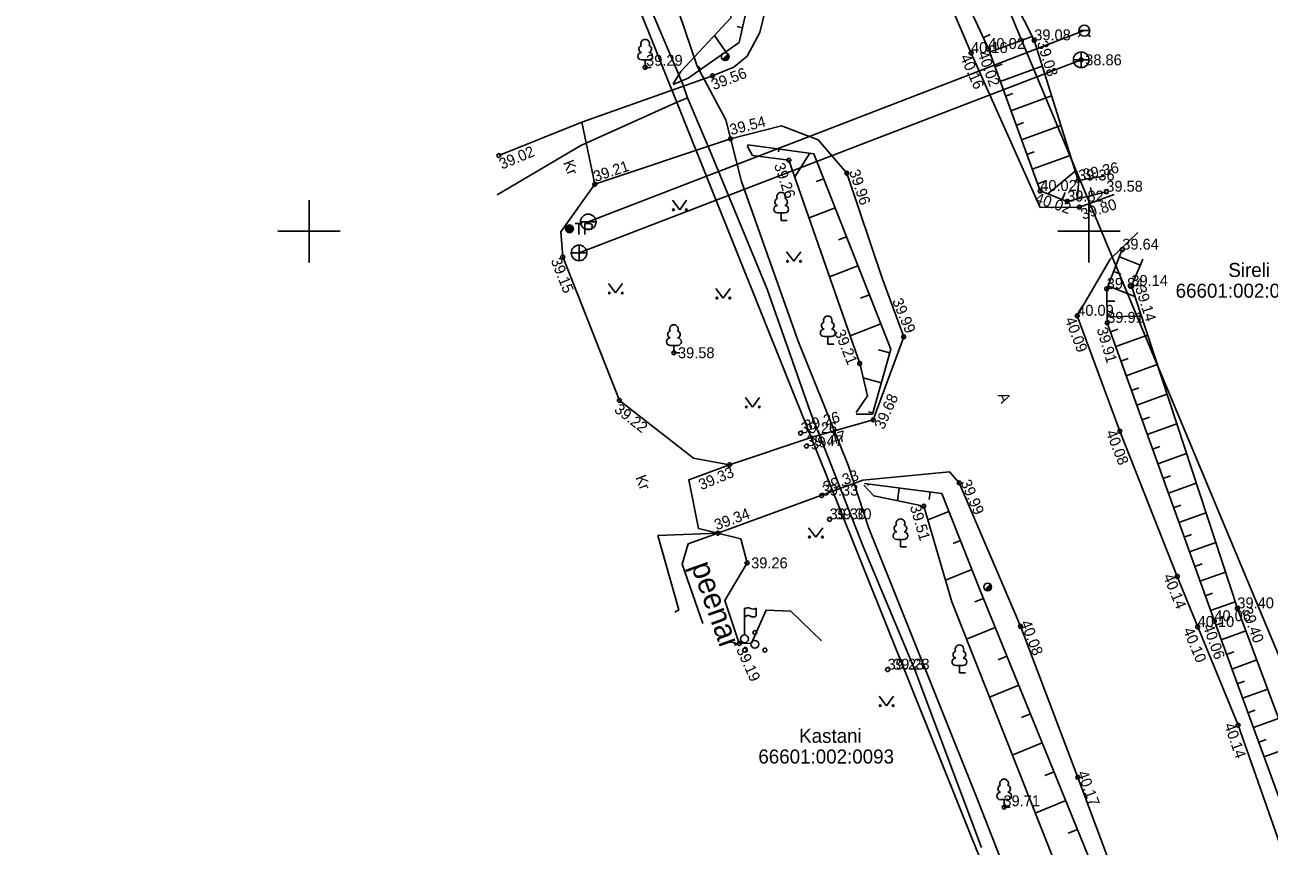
# Model space of a CAD drawing. Extents: x 627548 to 628052, y 6467984 to 6468802.
# Drawn here: x 627831.8 to 627911.6, y 6468260.5 to 6468313.2 of the extents above; entities that cross this region are included whole.
import ezdxf

# ---------------------------------------------------------------- set-up
doc = ezdxf.new("R2010")
doc.units = 0
for name, color, linetype in [('HALJASTUS', 7, 'Continuous'), ('KKAEV', 7, 'Continuous'), ('KORGUS-EH2000', 7, 'Continuous'), ('KTRASS', 7, 'Continuous'), ('MOOTKORG-EH2000', 7, 'Continuous'), ('MOOTMPUNKT', 7, 'Continuous'), ('PIIR', 7, 'Continuous'), ('POST', 7, 'Continuous'), ('PUU', 7, 'Continuous'), ('RAJATIS', 7, 'Continuous'), ('RELJEEF', 7, 'Continuous'), ('SITRASS', 7, 'Continuous'), ('TEE', 7, 'Continuous'), ('VKAEV', 7, 'Continuous'), ('VORK', 7, 'Continuous'), ('VTRASS', 7, 'Continuous')]:
    doc.layers.add(name, color=color, linetype=linetype)

msp = doc.modelspace()

# ---------------------------------------------------------------- linework, layer by layer
at = {"layer": 'HALJASTUS'}
for p, q in [((627873.299, 6468301.984), (627873.762, 6468301.377)), ((627873.762, 6468301.377), (627874.208, 6468301.984)), ((627880.62, 6468298.678), (627881.083, 6468298.071)), ((627881.083, 6468298.071), (627881.529, 6468298.678)), ((627869.19, 6468296.647), (627869.653, 6468296.04)), ((627869.653, 6468296.04), (627870.099, 6468296.647)), ((627876.086, 6468296.316), (627876.549, 6468295.71)), ((627876.549, 6468295.71), (627876.995, 6468296.316)), ((627877.975, 6468289.326), (627878.438, 6468288.72)), ((627878.438, 6468288.72), (627878.884, 6468289.326)), ((627882.025, 6468280.978), (627882.488, 6468280.372)), ((627882.488, 6468280.372), (627882.934, 6468280.978)), ((627886.559, 6468270.163), (627887.022, 6468269.556)), ((627887.022, 6468269.556), (627887.468, 6468270.163))]:
    msp.add_line(p, q, dxfattribs=at)
msp.add_lwpolyline([(627873.919, 6468278.628), (627874.303, 6468279.942), (627876.206, 6468280.62), (627877.677, 6468280.262), (627878.082, 6468278.718), (627876.666, 6468276.298), (627877.586, 6468273.55), (627878.366, 6468273.568), (627879.299, 6468275.694), (627880.884, 6468275.618), (627882.857, 6468273.714)], dxfattribs=at)
for centre in [(627873.361, 6468301.377), (627874.19, 6468301.377), (627880.682, 6468298.071), (627881.511, 6468298.071), (627869.252, 6468296.04), (627870.081, 6468296.04), (627876.148, 6468295.71), (627876.977, 6468295.71), (627878.037, 6468288.72), (627878.866, 6468288.72), (627882.087, 6468280.372), (627882.916, 6468280.372), (627886.621, 6468269.556), (627887.45, 6468269.556)]:
    msp.add_circle(centre, 0.055, dxfattribs=at)
at = {"layer": 'KKAEV'}
for p, q in [((627899.506, 6468310.497), (627899.506, 6468311.497)), ((627899.006, 6468310.997), (627900.006, 6468310.997)), ((627866.811, 6468298.611), (627867.811, 6468298.611)), ((627867.311, 6468298.111), (627867.311, 6468299.111))]:
    msp.add_line(p, q, dxfattribs=at)
for centre in [(627899.506, 6468310.997), (627867.311, 6468298.611)]:
    msp.add_circle(centre, 0.5, dxfattribs=at)
at = {"layer": 'KORGUS-EH2000'}
for centre in [(627871.551, 6468310.515), (627899.506, 6468310.997), (627875.866, 6468309.978), (627877.023, 6468305.93), (627862.168, 6468304.855), (627880.767, 6468304.558), (627884.478, 6468303.721), (627868.314, 6468303.013), (627899.39, 6468301.545), (627866.262, 6468298.348), (627888.125, 6468293.223), (627873.393, 6468292.203), (627885.303, 6468291.516), (627869.897, 6468289.144), (627886.174, 6468287.898), (627901.988, 6468287.172), (627876.962, 6468285.017), (627891.69, 6468283.856), (627889.411, 6468282.354), (627876.206, 6468280.62), (627878.082, 6468278.718), (627905.673, 6468277.849), (627895.618, 6468274.651), (627877.586, 6468273.55), (627909.567, 6468268.305), (627899.293, 6468264.957), (627894.568, 6468263.052)]:
    msp.add_circle(centre, 0.125, dxfattribs=at)
at = {"layer": 'KTRASS'}
msp.add_line((627867.311, 6468298.611), (627899.506, 6468310.997), dxfattribs=at)
at = {"layer": 'MOOTMPUNKT'}
for centre in [(627896.498, 6468312.249), (627892.446, 6468311.434), (627893.555, 6468311.693), (627899.309, 6468303.257), (627896.884, 6468302.582), (627901.118, 6468302.536), (627898.609, 6468301.907), (627902.143, 6468298.82), (627901.144, 6468296.301), (627902.726, 6468296.488), (627899.253, 6468294.574), (627901.175, 6468294.123), (627881.512, 6468287.043), (627881.89, 6468286.213), (627882.869, 6468283.039), (627883.368, 6468281.515), (627909.522, 6468275.801), (627906.975, 6468274.61), (627908.047, 6468274.979), (627887.093, 6468271.873)]:
    msp.add_circle(centre, 0.125, dxfattribs=at)
at = {"layer": 'PIIR'}
for p, q in [((627869.12, 6468319.4), (627897.87, 6468247.69)), ((627912.59, 6468271.79), (627893.5, 6468317.49))]:
    msp.add_line(p, q, dxfattribs=at)
at = {"layer": 'POST'}
for p, q in [((627876.506, 6468311.02), (627876.86, 6468311.373)), ((627867.051, 6468300.496), (627867.518, 6468300.496)), ((627867.284, 6468300.496), (627867.284, 6468299.796)), ((627867.684, 6468300.496), (627867.684, 6468299.796)), ((627893.334, 6468276.992), (627893.688, 6468277.345))]:
    msp.add_line(p, q, dxfattribs=at)
msp.add_lwpolyline([(627867.684, 6468300.496), (627867.984, 6468300.496), (627868.084, 6468300.463), (627868.118, 6468300.43), (627868.151, 6468300.363), (627868.151, 6468300.263), (627868.118, 6468300.196), (627868.084, 6468300.163), (627867.984, 6468300.13), (627867.684, 6468300.13)], dxfattribs=at)
for centre, radius in [((627876.683, 6468311.196), 0.25), ((627866.692, 6468300.149), 0.25), ((627866.692, 6468300.149), 0.225), ((627866.692, 6468300.149), 0.2), ((627866.692, 6468300.149), 0.175), ((627866.692, 6468300.149), 0.15), ((627866.692, 6468300.149), 0.125), ((627866.692, 6468300.149), 0.1), ((627866.692, 6468300.149), 0.075), ((627866.692, 6468300.149), 0.05), ((627866.692, 6468300.149), 0.025), ((627893.511, 6468277.168), 0.25)]:
    msp.add_circle(centre, radius, dxfattribs=at)
for centre, radius, start, end in [((627876.683, 6468311.196), 0.225, 224.85406, 45.03563), ((627876.683, 6468311.196), 0.2, 224.84272, 45.04698), ((627876.683, 6468311.196), 0.175, 224.82813, 45.06157), ((627876.683, 6468311.196), 0.15, 224.80867, 45.08103), ((627876.683, 6468311.196), 0.125, 224.78144, 45.10826), ((627876.683, 6468311.196), 0.1, 224.74058, 45.14911), ((627876.683, 6468311.196), 0.075, 224.67249, 45.2172), ((627876.683, 6468311.196), 0.05, 224.53632, 45.35338), ((627876.683, 6468311.196), 0.025, 224.12776, 45.76193), ((627893.511, 6468277.168), 0.225, 224.85406, 45.03563), ((627893.511, 6468277.168), 0.2, 224.84272, 45.04698), ((627893.511, 6468277.168), 0.175, 224.82813, 45.06157), ((627893.511, 6468277.168), 0.15, 224.80867, 45.08103), ((627893.511, 6468277.168), 0.125, 224.78144, 45.10826), ((627893.511, 6468277.168), 0.1, 224.74058, 45.14911), ((627893.511, 6468277.168), 0.075, 224.67249, 45.2172), ((627893.511, 6468277.168), 0.05, 224.53632, 45.35338), ((627893.511, 6468277.168), 0.025, 224.12776, 45.76193)]:
    msp.add_arc(centre, radius, start, end, dxfattribs=at)
at = {"layer": 'PUU'}
for p, q in [((627871.791, 6468310.99), (627871.311, 6468310.99)), ((627871.551, 6468310.515), (627871.551, 6468310.99)), ((627871.931, 6468310.515), (627871.551, 6468310.515)), ((627880.509, 6468301.173), (627880.029, 6468301.173)), ((627880.269, 6468300.698), (627880.269, 6468301.173)), ((627880.649, 6468300.698), (627880.269, 6468300.698)), ((627883.497, 6468293.238), (627883.017, 6468293.238)), ((627883.257, 6468292.763), (627883.257, 6468293.238)), ((627873.633, 6468292.678), (627873.153, 6468292.678)), ((627873.393, 6468292.203), (627873.393, 6468292.678)), ((627873.773, 6468292.203), (627873.393, 6468292.203)), ((627883.637, 6468292.763), (627883.257, 6468292.763)), ((627888.158, 6468280.227), (627887.678, 6468280.227)), ((627887.918, 6468279.752), (627887.918, 6468280.227)), ((627888.298, 6468279.752), (627887.918, 6468279.752)), ((627891.939, 6468272.132), (627891.459, 6468272.132)), ((627891.699, 6468271.657), (627891.699, 6468272.132)), ((627892.079, 6468271.657), (627891.699, 6468271.657)), ((627894.808, 6468263.527), (627894.328, 6468263.527)), ((627894.568, 6468263.052), (627894.568, 6468263.527)), ((627894.948, 6468263.052), (627894.568, 6468263.052))]:
    msp.add_line(p, q, dxfattribs=at)
for centre, radius in [((627878.579, 6468273.497), 0.25), ((627878.579, 6468274.247), 0.125), ((627877.929, 6468273.122), 0.125), ((627879.229, 6468273.122), 0.125)]:
    msp.add_circle(centre, radius, dxfattribs=at)
for centre, radius, start, end in [((627871.551, 6468312.035), 0.277, 332.5799, 207.4201), ((627871.314, 6468311.227), 0.238, 90.0016, 269.3953), ((627871.381, 6468311.688), 0.233, 109.02174, 253.14154), ((627871.721, 6468311.688), 0.233, 286.85082, 70.98591), ((627871.788, 6468311.227), 0.238, 270.6047, 89.9984), ((627880.269, 6468302.218), 0.277, 332.5799, 207.4201), ((627880.032, 6468301.41), 0.238, 90.0016, 269.3953), ((627880.099, 6468301.871), 0.233, 109.02174, 253.14154), ((627880.439, 6468301.871), 0.233, 286.85082, 70.98591), ((627880.506, 6468301.41), 0.238, 270.6047, 89.9984), ((627883.257, 6468294.283), 0.277, 332.5799, 207.4201), ((627873.223, 6468293.376), 0.233, 109.02174, 253.14154), ((627873.393, 6468293.723), 0.277, 332.5799, 207.4201), ((627873.563, 6468293.376), 0.233, 286.85082, 70.98591), ((627883.02, 6468293.475), 0.238, 90.0016, 269.3953), ((627883.087, 6468293.936), 0.233, 109.02174, 253.14154), ((627883.427, 6468293.936), 0.233, 286.85082, 70.98591), ((627883.494, 6468293.475), 0.238, 270.6047, 89.9984), ((627873.156, 6468292.915), 0.238, 90.0016, 269.3953), ((627873.63, 6468292.915), 0.238, 270.6047, 89.9984), ((627887.748, 6468280.925), 0.233, 109.02174, 253.14154), ((627887.918, 6468281.272), 0.277, 332.5799, 207.4201), ((627888.088, 6468280.925), 0.233, 286.85082, 70.98591), ((627887.681, 6468280.464), 0.238, 90.0016, 269.3953), ((627888.155, 6468280.464), 0.238, 270.6047, 89.9984), ((627891.529, 6468272.83), 0.233, 109.02174, 253.14154), ((627891.699, 6468273.177), 0.277, 332.5799, 207.4201), ((627891.869, 6468272.83), 0.233, 286.85082, 70.98591), ((627891.462, 6468272.369), 0.238, 90.0016, 269.3953), ((627891.936, 6468272.369), 0.238, 270.6047, 89.9984), ((627894.398, 6468264.225), 0.233, 109.02174, 253.14154), ((627894.568, 6468264.572), 0.277, 332.5799, 207.4201), ((627894.738, 6468264.225), 0.233, 286.85082, 70.98591), ((627894.331, 6468263.764), 0.238, 90.0016, 269.3953), ((627894.805, 6468263.764), 0.238, 270.6047, 89.9984)]:
    msp.add_arc(centre, radius, start, end, dxfattribs=at)
at = {"layer": 'RAJATIS'}
for p, q in [((627877.922, 6468274.094), (627877.922, 6468275.844)), ((627878.675, 6468275.813), (627878.675, 6468275.313))]:
    msp.add_line(p, q, dxfattribs=at)
msp.add_circle((627877.922, 6468273.844), 0.25, dxfattribs=at)
for centre, radius, start, end in [((627878.145, 6468275.559), 0.288, 57.89407, 140.73656), ((627878.145, 6468275.059), 0.288, 57.89407, 140.73656), ((627878.479, 6468276.092), 0.341, 237.89407, 305.02189), ((627878.479, 6468275.592), 0.341, 237.89407, 305.02189)]:
    msp.add_arc(centre, radius, start, end, dxfattribs=at)
at = {"layer": 'RELJEEF'}
for p, q in [((627877.784, 6468313.056), (627877.453, 6468313.129)), ((627876.728, 6468311.519), (627875.995, 6468312.565)), ((627893.226, 6468312.405), (627893.68, 6468312.615)), ((627893.629, 6468311.491), (627896.374, 6468312.494)), ((627875.09, 6468310.371), (627874.943, 6468310.581)), ((627893.972, 6468310.551), (627894.442, 6468310.723)), ((627894.315, 6468309.612), (627897.014, 6468310.598)), ((627894.659, 6468308.673), (627895.128, 6468308.844)), ((627895.002, 6468307.734), (627897.611, 6468308.687)), ((627895.345, 6468306.794), (627895.815, 6468306.966)), ((627895.688, 6468305.855), (627898.209, 6468306.776)), ((627878.135, 6468305.54), (627878.12, 6468305.425)), ((627880.117, 6468305.276), (627880.093, 6468305.089)), ((627882.1, 6468305.012), (627881.139, 6468303.489)), ((627896.031, 6468304.916), (627896.501, 6468305.087)), ((627896.374, 6468303.977), (627898.806, 6468304.865)), ((627883.003, 6468303.37), (627882.522, 6468303.182)), ((627896.718, 6468303.037), (627897.187, 6468303.209)), ((627897.364, 6468302.394), (627899.123, 6468303.853)), ((627899.252, 6468302.068), (627899.357, 6468303.265)), ((627898.295, 6468302.03), (627898.477, 6468302.495)), ((627900.222, 6468302.311), (627900.1, 6468302.796)), ((627883.733, 6468301.508), (627882.056, 6468300.851)), ((627884.463, 6468299.646), (627883.938, 6468299.441)), ((627885.193, 6468297.784), (627883.371, 6468297.07)), ((627901.959, 6468298.355), (627903.353, 6468297.802)), ((627901.59, 6468297.426), (627902.055, 6468297.241)), ((627901.221, 6468296.496), (627902.948, 6468295.811)), ((627885.923, 6468295.922), (627885.355, 6468295.7)), ((627901.155, 6468295.511), (627901.655, 6468295.518)), ((627901.169, 6468294.511), (627903.365, 6468294.542)), ((627886.653, 6468294.06), (627884.686, 6468293.289)), ((627901.382, 6468293.547), (627901.852, 6468293.716)), ((627901.72, 6468292.606), (627903.761, 6468293.339)), ((627887.228, 6468292.191), (627886.51, 6468292.393)), ((627902.057, 6468291.665), (627902.528, 6468291.834)), ((627902.395, 6468290.723), (627904.385, 6468291.438)), ((627886.685, 6468290.266), (627885.523, 6468290.594)), ((627902.733, 6468289.782), (627903.204, 6468289.951)), ((627903.071, 6468288.841), (627905.01, 6468289.537)), ((627886.142, 6468288.341), (627885.87, 6468288.418)), ((627903.409, 6468287.9), (627903.879, 6468288.069)), ((627903.747, 6468286.959), (627905.634, 6468287.636)), ((627904.085, 6468286.017), (627904.555, 6468286.186)), ((627904.422, 6468285.076), (627906.258, 6468285.735)), ((627904.76, 6468284.135), (627905.231, 6468284.304)), ((627885.851, 6468283.786), (627885.837, 6468283.683)), ((627887.834, 6468283.523), (627887.725, 6468282.702)), ((627889.816, 6468283.261), (627889.754, 6468282.788)), ((627905.098, 6468283.194), (627906.883, 6468283.835)), ((627905.436, 6468282.253), (627905.907, 6468282.422)), ((627891.027, 6468282.009), (627889.669, 6468281.472)), ((627905.774, 6468281.311), (627907.507, 6468281.934)), ((627891.763, 6468280.15), (627891.304, 6468279.968)), ((627906.112, 6468280.37), (627906.582, 6468280.539)), ((627906.45, 6468279.429), (627908.132, 6468280.033)), ((627906.787, 6468278.488), (627907.258, 6468278.657)), ((627892.499, 6468278.29), (627890.798, 6468277.617)), ((627907.125, 6468277.547), (627908.756, 6468278.132)), ((627893.241, 6468276.433), (627892.694, 6468276.21)), ((627907.463, 6468276.606), (627907.934, 6468276.774)), ((627907.801, 6468275.664), (627909.381, 6468276.231)), ((627893.995, 6468274.58), (627892.151, 6468273.829)), ((627908.141, 6468274.724), (627908.61, 6468274.896)), ((627908.484, 6468273.785), (627910.061, 6468274.362)), ((627908.828, 6468272.846), (627909.298, 6468273.018)), ((627894.75, 6468272.728), (627894.191, 6468272.5)), ((627909.172, 6468271.907), (627910.764, 6468272.49)), ((627895.505, 6468270.876), (627893.621, 6468270.109)), ((627909.516, 6468270.968), (627909.986, 6468271.14)), ((627909.86, 6468270.029), (627911.466, 6468270.617)), ((627896.259, 6468269.024), (627895.688, 6468268.791)), ((627910.204, 6468269.09), (627910.674, 6468269.262)), ((627910.548, 6468268.151), (627912.168, 6468268.744)), ((627910.892, 6468267.212), (627911.362, 6468267.384)), ((627897.014, 6468267.172), (627895.09, 6468266.388)), ((627911.236, 6468266.273), (627912.871, 6468266.872)), ((627897.768, 6468265.32), (627897.185, 6468265.082)), ((627898.523, 6468263.467), (627896.559, 6468262.667)), ((627899.277, 6468261.615), (627898.682, 6468261.373))]:
    msp.add_line(p, q, dxfattribs=at)
for points in [[(627872.236, 6468374.908), (627868.619, 6468372.938), (627874.455, 6468357.057), (627883.906, 6468332.57), (627893.555, 6468311.693), (627896.884, 6468302.582), (627898.609, 6468301.907), (627901.118, 6468302.536)], [(627872.45, 6468373.949), (627870.95, 6468372.302), (627876.843, 6468358.333), (627885.562, 6468333.781), (627896.498, 6468312.249), (627899.309, 6468303.257), (627900.953, 6468303.542)], [(627873.347, 6468309.45), (627873.83, 6468310.241), (627877.069, 6468313.719), (627876.234, 6468317.068), (627866.378, 6468340.34), (627864.296, 6468344.897), (627863.023, 6468347.157)], [(627873.346, 6468309.415), (627874.307, 6468309.823), (627877.573, 6468312.111), (627878.237, 6468315.09), (627877.354, 6468317.55), (627868.906, 6468339.736), (627866.293, 6468345.533)], [(627878.118, 6468305.428), (627878.438, 6468304.86), (627880.767, 6468304.558), (627885.303, 6468291.516), (627885.799, 6468289.434), (627885.077, 6468288.359)], [(627878.135, 6468305.54), (627882.374, 6468304.975), (627887.294, 6468292.425), (627886.12, 6468288.264), (627885.077, 6468288.259)], [(627902.143, 6468298.82), (627901.144, 6468296.301), (627901.175, 6468294.123), (627908.047, 6468274.979), (627912.743, 6468262.16), (627914.112, 6468261.408), (627915.818, 6468261.36), (627916.836, 6468261.596)], [(627903.454, 6468298.207), (627902.726, 6468296.488), (627909.522, 6468275.801), (627914.133, 6468263.505), (627915.522, 6468263.197)], [(627885.568, 6468283.7), (627886.202, 6468283.017), (627889.411, 6468282.354), (627891.208, 6468276.218), (627898.343, 6468258.151), (627903.422, 6468243.916), (627907.954, 6468231.1), (627910.914, 6468222.474), (627911.053, 6468221.789), (627909.271, 6468220.222)], [(627908.534, 6468218.999), (627909.815, 6468219.296), (627912.114, 6468220.934), (627912.832, 6468222.373), (627910.285, 6468232.435), (627905.813, 6468244.778), (627900.201, 6468259.348), (627892.991, 6468277.046), (627890.571, 6468283.161), (627885.622, 6468283.816)]]:
    msp.add_lwpolyline(points, dxfattribs=at)
at = {"layer": 'SITRASS'}
for points in [[(627895.041, 6468257.946), (627892.765, 6468263.751), (627885.861, 6468280.997), (627884.574, 6468284.991), (627881.355, 6468292.946), (627877.718, 6468303.187), (627876.72, 6468307.148), (627874.885, 6468310.594), (627872.6, 6468317.358), (627865.068, 6468335.844), (627862.702, 6468343.386), (627859.888, 6468348.841), (627858.632, 6468350.621)], [(627893.107, 6468260.449), (627888.841, 6468271.867), (627885.53, 6468279.764), (627882.135, 6468288.441), (627879.374, 6468296.292), (627875.722, 6468305.138), (627874.264, 6468308.557), (627873.961, 6468309.445), (627871.602, 6468314.968), (627869.468, 6468319.018), (627867.454, 6468324.77), (627864.183, 6468335.69), (627861.634, 6468344.011), (627861.623, 6468344.046)], [(627874.264, 6468308.557), (627873.441, 6468308.226), (627867.426, 6468305.507), (627862.053, 6468302.34)]]:
    msp.add_lwpolyline(points, dxfattribs=at)
at = {"layer": 'TEE'}
for points in [[(627773.875, 6468550.47), (627771.331, 6468547.778), (627770.184, 6468544.969), (627779.724, 6468530.382), (627790.194, 6468514.89), (627795.603, 6468506.268), (627810.358, 6468482.16), (627820.252, 6468465.61), (627824.787, 6468457.176), (627842.022, 6468424.68), (627853.219, 6468402.014), (627861.194, 6468384.862), (627867.233, 6468371.168), (627873.073, 6468356.381), (627889.258, 6468318.908), (627892.446, 6468311.434), (627896.87, 6468301.517), (627899.405, 6468301.54), (627901.626, 6468302.361)], [(627850.995, 6468383.192), (627865.917, 6468348.418), (627869.848, 6468339.563), (627875.198, 6468325.862), (627878.868, 6468316.397), (627879.191, 6468315.536), (627879.247, 6468314.16), (627878.907, 6468312.752), (627878.096, 6468311.241), (627877.224, 6468310.534), (627875.866, 6468309.978), (627867.479, 6468306.988), (627868.314, 6468303.013), (627877.023, 6468305.93), (627880.299, 6468306.759), (627882.65, 6468305.874), (627884.478, 6468303.721), (627886.739, 6468296.981), (627888.125, 6468293.223), (627886.174, 6468287.898), (627882.32, 6468286.813)], [(627867.479, 6468306.988), (627862.168, 6468304.855)], [(627866.143, 6468299.952), (627868.314, 6468303.013)], [(627882.32, 6468286.813), (627876.962, 6468285.017), (627874.642, 6468285.428), (627869.897, 6468289.144), (627866.262, 6468298.348), (627866.143, 6468299.952)], [(627917.783, 6468261.132), (627915.406, 6468260.556), (627912.243, 6468260.69), (627909.567, 6468268.305), (627905.673, 6468277.849), (627901.988, 6468287.172), (627899.253, 6468294.574), (627901.367, 6468298.21), (627903.149, 6468299.908)], [(627876.962, 6468285.017), (627874.347, 6468284.039), (627874.971, 6468280.918), (627876.206, 6468280.62), (627885.515, 6468284.028), (627891.073, 6468284.568), (627891.69, 6468283.856), (627895.618, 6468274.651), (627899.293, 6468264.957), (627902.839, 6468255.421), (627906.501, 6468245.876), (627910.238, 6468235.996), (627913.742, 6468226.218), (627914.642, 6468222.923), (627913.271, 6468221.098), (627910.191, 6468218.684), (627908.74, 6468217.99)], [(627876.206, 6468280.62), (627872.364, 6468280.485), (627873.713, 6468275.697), (627873.443, 6468275.566)], [(627873.919, 6468278.628), (627875.251, 6468274.826)]]:
    msp.add_lwpolyline(points, dxfattribs=at)
at = {"layer": 'VKAEV'}
for p, q in [((627899.352, 6468312.87), (627900.052, 6468312.87)), ((627899.455, 6468312.623), (627899.315, 6468312.483)), ((627899.949, 6468312.623), (627900.089, 6468312.483)), ((627867.398, 6468300.601), (627868.398, 6468300.601))]:
    msp.add_line(p, q, dxfattribs=at)
for centre, radius in [((627899.702, 6468312.87), 0.35), ((627867.898, 6468300.601), 0.5)]:
    msp.add_circle(centre, radius, dxfattribs=at)
at = {"layer": 'VORK'}
for p, q in [((627850, 6468302), (627850, 6468298)), ((627900, 6468302), (627900, 6468298)), ((627848, 6468300), (627852, 6468300)), ((627898, 6468300), (627902, 6468300))]:
    msp.add_line(p, q, dxfattribs=at)
at = {"layer": 'VTRASS'}
msp.add_line((627899.702, 6468312.87), (627867.898, 6468300.601), dxfattribs=at)

# ---------------------------------------------------------------- texts
at = {"layer": 'HALJASTUS'}
msp.add_text('peenar', height=1.4, rotation=289.59009, dxfattribs=at).set_placement((627874.475, 6468278.539))
at = {"layer": 'KORGUS-EH2000'}
for s, rotation, p in [('39.08', 287.47764, (627896.666, 6468312.096)), ('40.16', 294.22751, (627891.724, 6468311.171)), ('40.02', 289.90761, (627892.859, 6468311.414)), (' 39.56', 20.7179, (627875.698, 6468308.957)), (' 39.54', 14.20073, (627876.809, 6468306.097)), (' 39.02', 22.6427, (627862.12, 6468303.853)), (' 39.21', 18.5178, (627868.116, 6468303.072)), (' 39.26', 288.60275, (627879.719, 6468304.499)), (' 39.96', 288.54454, (627884.529, 6468304.08)), ('39.36', 11.96502, (627899.683, 6468303.289)), ('40.02', 341.32187, (627896.491, 6468301.843)), (' 39.80', 17.65633, (627899.369, 6468300.652)), (' 39.15', 291.5509, (627865.388, 6468298.373)), ('39.14', 287.82957, (627902.959, 6468296.365)), (' 39.99', 292.97136, (627887.268, 6468295.77)), ('40.09', 290.7957, (627898.454, 6468294.343)), (' 39.21', 292.04544, (627883.568, 6468293.771)), ('39.91', 286.60337, (627900.491, 6468293.727)), (' 39.22', 321.93408, (627869.306, 6468288.621)), (' 39.68', 66.08306, (627886.74, 6468286.993)), ('39.26', 15.4706, (627881.838, 6468287.163)), ('39.47', 15.12996, (627882.226, 6468285.945)), (' 40.08', 291.56686, (627900.978, 6468287.339)), (' 39.33', 22.5664, (627874.911, 6468283.279)), ('39.33', 21.3767, (627883.133, 6468283.228)), (' 39.99', 293.10914, (627891.655, 6468284.126)), (' 39.51', 286.32329, (627888.442, 6468282.581)), (' 39.34', 20.11048, (627875.888, 6468280.713)), (' 40.14', 292.19571, (627904.649, 6468278.099)), ('39.40', 290.26353, (627909.782, 6468275.709)), (' 40.08', 290.76174, (627895.514, 6468275.133)), ('40.10', 292.60221, (627906.024, 6468274.407)), ('40.06', 289.80249, (627907.302, 6468274.657)), (' 39.19', 294.07928, (627877.266, 6468273.407)), (' 40.14', 289.36207, (627908.577, 6468268.561)), (' 40.17', 290.39785, (627899.157, 6468265.481))]:
    msp.add_text(s, height=0.7, rotation=rotation, dxfattribs=at).set_placement(p)
for s, p in [(' 39.29', (627871.348, 6468310.618)), (' 38.86', (627899.506, 6468310.647)), (' 39.58', (627873.393, 6468291.853)), ('39.30', (627883.718, 6468281.515)), (' 39.26', (627878.082, 6468278.368)), ('39.23', (627887.443, 6468271.873)), (' 39.71', (627894.261, 6468263.105))]:
    msp.add_text(s, height=0.7, dxfattribs=at).set_placement(p)
at = {"layer": 'MOOTKORG-EH2000'}
for s, p in [('39.08', (627896.498, 6468312.249)), ('40.16', (627892.446, 6468311.434)), ('40.02', (627893.555, 6468311.693)), ('39.36', (627899.309, 6468303.257)), ('40.02', (627896.884, 6468302.582)), ('39.58', (627901.118, 6468302.536)), ('39.82', (627898.609, 6468301.907)), ('39.64', (627902.143, 6468298.82)), ('39.84', (627901.144, 6468296.301)), ('39.14', (627902.726, 6468296.488)), ('40.09', (627899.253, 6468294.574)), ('39.91', (627901.175, 6468294.123)), ('39.26', (627881.512, 6468287.043)), ('39.47', (627881.89, 6468286.213)), ('39.33', (627882.869, 6468283.039)), ('39.30', (627883.368, 6468281.515)), ('39.40', (627909.522, 6468275.801)), ('40.10', (627906.975, 6468274.61)), ('40.06', (627908.047, 6468274.979)), ('39.23', (627887.093, 6468271.873))]:
    msp.add_text(s, height=0.7, dxfattribs=at).set_placement(p)
at = {"layer": 'PIIR'}
for s, p in [('Sireli', (627908.943, 6468297.065)), ('66601:002:0267', (627905.565, 6468295.734)), ('Kastani', (627881.421, 6468267.177)), ('66601:002:0093', (627878.805, 6468265.846))]:
    msp.add_text(s, height=0.9, dxfattribs=at).set_placement(p)
at = {"layer": 'TEE'}
for s, rotation, p in [('Kr', 291.35802, (627866.273, 6468304.405)), ('A', 292.11557, (627894.143, 6468289.483)), ('Kr', 291.35802, (627870.911, 6468284.199))]:
    msp.add_text(s, height=0.7, rotation=rotation, dxfattribs=at).set_placement(p)

doc.saveas('drawing.dxf')
